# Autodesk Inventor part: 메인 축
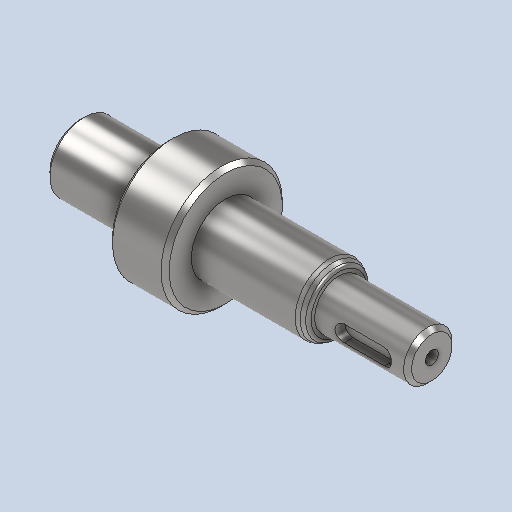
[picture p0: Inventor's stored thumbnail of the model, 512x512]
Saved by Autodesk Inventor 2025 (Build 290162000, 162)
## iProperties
Created: 2024-07
Part Number: 메인 축
Material: 강철, 연강
Document SubType Name: Modeling
Designer: hsj03
Density: 7.86 g/cm^3
Appearance: 기본값
Author: jhkim
Revision Number: 1
Sending System: Autodesk Inventor 2025
Preprocessor: ST-DEVELOPER v20
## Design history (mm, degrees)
feature "솔리드1"
node "솔리드2"
